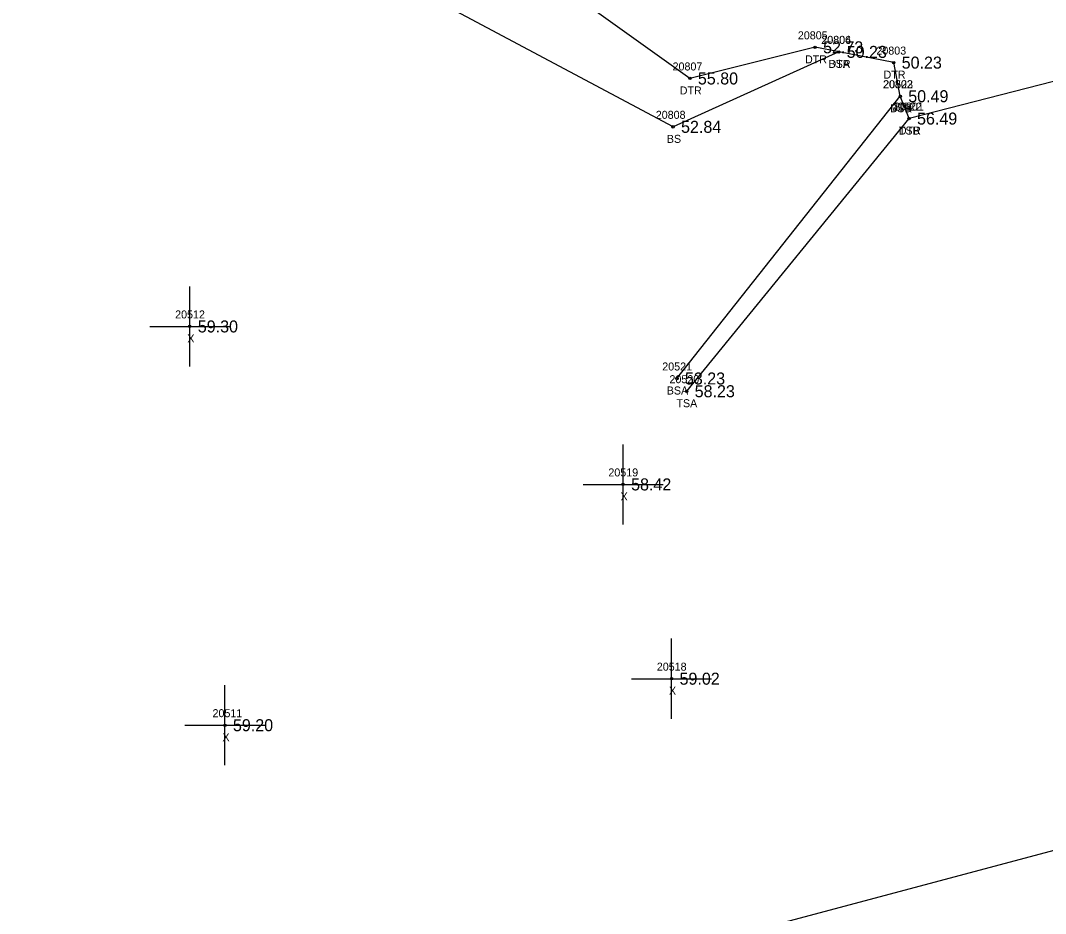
# Model space of a CAD drawing. Extents: x 2420351 to 2422725, y 845330 to 846558.
# Drawn here: x 2421379.3 to 2421507.3, y 845732.5 to 845844 of the extents above; entities that cross this region are included whole.
import ezdxf

# ---------------------------------------------------------------- set-up
doc = ezdxf.new("R2010")
doc.units = 0
for name, color, linetype in [('RD_DTM_BkLn2', 7, 'Continuous'), ('RD_DTM_BkLn_txCode', 7, 'Continuous'), ('RD_EX_H2O', 7, 'Continuous'), ('RD_EX_H2O_txCode', 7, 'Continuous'), ('RD_EX_Misc', 7, 'Continuous'), ('RD_EX_Misc_txCode', 7, 'Continuous'), ('RD_EX_TX_H2O_ELEV', 7, 'Continuous'), ('RD_EX_TX_Misc_ELEV', 7, 'Continuous'), ('RD_SMD_Locator', 7, 'Continuous')]:
    doc.layers.add(name, color=color, linetype=linetype)

msp = doc.modelspace()

# ---------------------------------------------------------------- linework, layer by layer
at = {"layer": 'RD_DTM_BkLn2'}
for p, q in [((2421461.26, 845799.31), (2421489.16, 845834.56)), ((2421462.48, 845797.72), (2421490.26, 845831.77))]:
    msp.add_line(p, q, dxfattribs=at)
msp.add_lwpolyline([(2421481.47, 845840.1), (2421460.78, 845830.74), (2421388.51, 845869.26)], dxfattribs=at)
at = {"layer": 'RD_EX_H2O'}
for points in [[(2421712.23, 845851.64), (2421696.17, 845853.46), (2421673.72, 845844.59), (2421672.85, 845833.86), (2421657.19, 845821.05), (2421639.52, 845822.79), (2421628.75, 845828.72), (2421620.88, 845834.5), (2421598.01, 845848.76), (2421559.66, 845849.82), (2421519.66, 845839.33), (2421490.26, 845831.77), (2421489.16, 845834.56), (2421488.34, 845838.76), (2421481.47, 845840.1), (2421478.52, 845840.67), (2421462.88, 845836.78), (2421401.68, 845880.53), (2421390.37, 845914.71), (2421413.41, 845969.29), (2421455.53, 845995.93), (2421500.71, 846029.14), (2421506.65, 846045.11), (2421509.82, 846047.43)], [(2421348.44, 845711.4), (2421408.11, 845718.43), (2421468.58, 845729.77), (2421526.52, 845745.24), (2421541.81, 845745.64), (2421549.75, 845745.7), (2421570.45, 845751.87), (2421591.88, 845757.66), (2421599.3, 845765.73), (2421650.04, 845787.07), (2421668.02, 845786.79), (2421719.15, 845813.59), (2421740.13, 845828.42)]]:
    msp.add_lwpolyline(points, dxfattribs=at)
at = {"layer": 'RD_EX_Misc'}
for p, q in [((2421400.41, 845800.81), (2421400.41, 845810.81)), ((2421395.41, 845805.81), (2421405.41, 845805.81)), ((2421454.54, 845781.08), (2421454.54, 845791.08)), ((2421449.54, 845786.08), (2421459.54, 845786.08)), ((2421460.59, 845756.82), (2421460.59, 845766.82)), ((2421455.59, 845761.82), (2421465.59, 845761.82)), ((2421404.8, 845751.01), (2421404.8, 845761.01)), ((2421399.8, 845756.01), (2421409.8, 845756.01))]:
    msp.add_line(p, q, dxfattribs=at)
at = {"layer": 'RD_SMD_Locator'}
for centre in [(2421478.52, 845840.67), (2421481.47, 845840.1), (2421481.47, 845840.1), (2421488.34, 845838.76), (2421462.88, 845836.78), (2421489.16, 845834.56), (2421489.16, 845834.56), (2421490.26, 845831.77), (2421490.26, 845831.77), (2421460.78, 845830.74), (2421400.41, 845805.81), (2421461.26, 845799.31), (2421462.48, 845797.72), (2421454.54, 845786.08), (2421460.59, 845761.82), (2421404.8, 845756.01)]:
    msp.add_circle(centre, 0.15, dxfattribs=at)

# ---------------------------------------------------------------- texts
at = {"layer": 'RD_DTM_BkLn_txCode'}
for s, p in [('20806', (2421479.29, 845841.1)), ('BSA', (2421480.2, 845838.1)), ('20523', (2421487.04, 845835.56)), ('BSB', (2421487.9, 845832.56)), ('20522', (2421488.14, 845832.77)), ('20808', (2421458.62, 845831.74)), ('TSB', (2421488.99, 845829.77)), ('BS', (2421460, 845828.74)), ('20521', (2421459.43, 845800.31)), ('20520', (2421460.33, 845798.72)), ('BSA', (2421459.99, 845797.31)), ('TSA', (2421461.2, 845795.72))]:
    msp.add_text(s, height=1, dxfattribs=at).set_placement(p)
at = {"layer": 'RD_EX_H2O_txCode'}
for s, p in [('20805', (2421476.37, 845841.67)), ('20804', (2421479.31, 845841.1)), ('20803', (2421486.18, 845839.76)), ('DTR', (2421477.26, 845838.67)), ('20807', (2421460.72, 845837.78)), ('DTR', (2421480.2, 845838.1)), ('DTR', (2421487.07, 845836.76)), ('DTR', (2421461.61, 845834.78)), ('20802', (2421487, 845835.56)), ('DTR', (2421487.89, 845832.56)), ('20801', (2421488.38, 845832.77)), ('DTR', (2421488.99, 845829.77))]:
    msp.add_text(s, height=1, dxfattribs=at).set_placement(p)
at = {"layer": 'RD_EX_Misc_txCode'}
for s, p in [('20512', (2421398.58, 845806.81)), ('X', (2421400.1, 845803.81)), ('20519', (2421452.7, 845787.08)), ('X', (2421454.22, 845784.08)), ('20518', (2421458.75, 845762.82)), ('X', (2421460.27, 845759.82)), ('20511', (2421403.25, 845757.01)), ('X', (2421404.49, 845754.01))]:
    msp.add_text(s, height=1, dxfattribs=at).set_placement(p)
at = {"layer": 'RD_EX_TX_H2O_ELEV'}
for s, p in [('52.73', (2421479.52, 845839.92)), ('50.23', (2421482.47, 845839.35)), ('50.23', (2421489.34, 845838.01)), ('55.80', (2421463.88, 845836.03)), ('50.49', (2421490.16, 845833.81)), ('56.49', (2421491.26, 845831.02))]:
    msp.add_text(s, height=1.5, dxfattribs=at).set_placement(p)
at = {"layer": 'RD_EX_TX_Misc_ELEV'}
for s, p in [('50.23', (2421482.47, 845839.35)), ('50.49', (2421490.16, 845833.81)), ('56.49', (2421491.26, 845831.02)), ('52.84', (2421461.78, 845829.99)), ('59.30', (2421401.41, 845805.06)), ('53.23', (2421462.26, 845798.56)), ('58.23', (2421463.48, 845796.97)), ('58.42', (2421455.54, 845785.33)), ('59.02', (2421461.59, 845761.07)), ('59.20', (2421405.8, 845755.26))]:
    msp.add_text(s, height=1.5, dxfattribs=at).set_placement(p)

doc.saveas('drawing.dxf')
